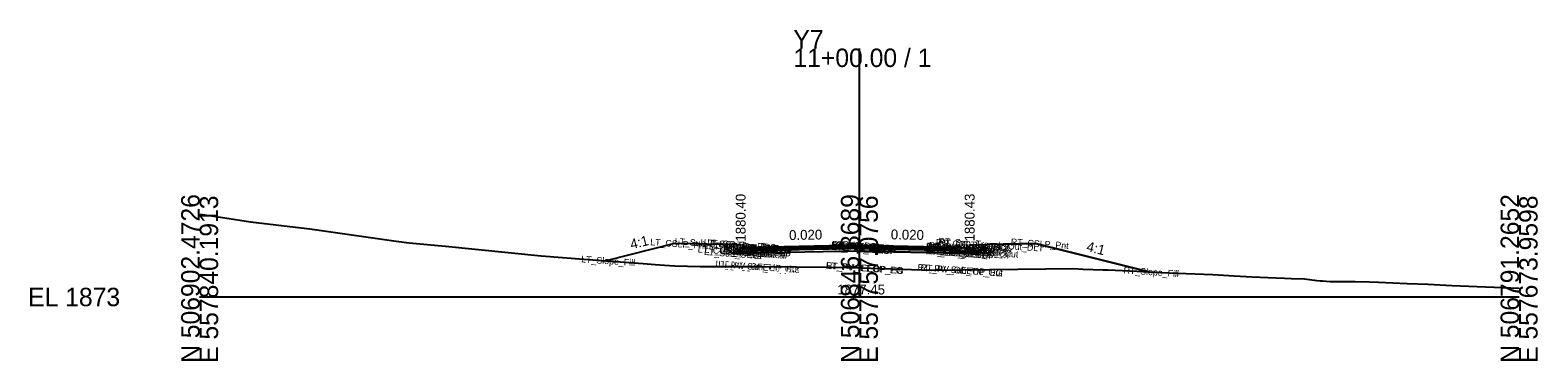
# Model space of a CAD drawing. Extents: x -26 to 557959, y -10 to 506992.
# Drawn here: x -25.7 to 202.8, y 990.3 to 1040.5 of the extents above; entities that cross this region are included whole.
import ezdxf

# ---------------------------------------------------------------- set-up
doc = ezdxf.new("R2010")
doc.units = 0
for name, color, linetype in [('Default', 7, 'Continuous'), ('Exist Cross Section Cell', 7, 'Continuous'), ('Exist XS Center Line Elevation Label', 7, 'Continuous'), ('Exist XS Ground Line', 7, 'Continuous'), ('Prop CMT Conc Surface', 7, 'Continuous'), ('Prop CMT Concrete Structures', 7, 'Continuous'), ('Prop CMT Pvmt Course 1', 7, 'Continuous'), ('Prop CMT Pvmt Course 1 CG', 7, 'Continuous'), ('Prop CMT Pvmt Course 1 Wedge', 7, 'Continuous'), ('Prop CMT Pvmt Course 2', 7, 'Continuous'), ('Prop CMT Pvmt Course 2 Wedge', 7, 'Continuous'), ('Prop CMT Pvmt Course 3', 7, 'Continuous'), ('Prop CMT Pvmt Course 3 Wedge', 7, 'Continuous'), ('Prop CMT Pvmt Surface', 7, 'Continuous'), ('Prop CMT Pvmt Wedge Surface 1', 7, 'Continuous'), ('Prop CMT Pvmt Wedge Surface 2', 7, 'Continuous'), ('Prop CMT Pvmt Wedge Surface 3', 7, 'Continuous'), ('Prop CMT Slope Grass', 7, 'Continuous'), ('Prop CMT Subgrade Earthwork', 7, 'Continuous'), ('Prop XS Earthwork Shape', 7, 'Continuous'), ('Prop XS Hydro Elevations', 7, 'Continuous'), ('Prop XS SE Text', 7, 'Continuous'), ('Prop XS Side Slope Text', 7, 'Continuous'), ('Typical Text Asphalt at Bridge Approach CELL', 7, 'Continuous')]:
    doc.layers.add(name, color=color, linetype=linetype)

msp = doc.modelspace()

# ---------------------------------------------------------------- linework, layer by layer
at = {"layer": 'Exist Cross Section Cell'}
for p, q in [((100, 1000), (100, 1037.69)), ((0, 1000), (100, 1000)), ((100, 1000), (200, 1000))]:
    msp.add_line(p, q, dxfattribs=at)
at = {"layer": 'Exist XS Ground Line'}
for p, q in [((0, 1012.56), (0.41, 1012.51)), ((0.41, 1012.51), (3.8, 1011.99)), ((3.8, 1011.99), (7.72, 1011.38)), ((7.72, 1011.38), (15.4, 1010.47)), ((15.4, 1010.47), (16.71, 1010.33)), ((16.71, 1010.33), (29.77, 1008.49)), ((29.77, 1008.49), (31.75, 1008.22)), ((31.75, 1008.22), (37.25, 1007.73)), ((37.25, 1007.73), (51.75, 1006.26)), ((51.75, 1006.26), (58.24, 1005.74)), ((58.24, 1005.74), (67.24, 1005.08)), ((67.24, 1005.08), (69.06, 1004.94)), ((69.06, 1004.94), (70.46, 1004.81)), ((70.46, 1004.81), (72.01, 1004.73)), ((72.01, 1004.73), (75.86, 1004.63)), ((75.86, 1004.63), (85.17, 1004.62)), ((85.17, 1004.62), (95.78, 1004.52)), ((95.78, 1004.52), (100.23, 1004.44)), ((100.23, 1004.44), (110.96, 1004.08)), ((110.96, 1004.08), (115.55, 1004.1)), ((115.55, 1004.1), (132.5, 1004.3)), ((132.5, 1004.3), (133.88, 1004.24)), ((133.88, 1004.24), (136.97, 1004.1)), ((136.97, 1004.1), (137.34, 1004.11)), ((137.34, 1004.11), (137.65, 1004.1)), ((137.65, 1004.1), (142.05, 1003.94)), ((142.05, 1003.94), (146.83, 1003.65)), ((146.83, 1003.65), (153.56, 1003.43)), ((153.56, 1003.43), (156.8, 1003.21)), ((156.8, 1003.21), (159.52, 1003.07)), ((159.52, 1003.07), (160.76, 1003.03)), ((160.76, 1003.03), (161.9, 1002.96)), ((161.9, 1002.96), (164.45, 1002.85)), ((164.45, 1002.85), (165.45, 1002.81)), ((165.45, 1002.81), (167.49, 1002.74)), ((167.49, 1002.74), (169.35, 1002.48)), ((169.35, 1002.48), (169.82, 1002.44)), ((169.82, 1002.44), (170.2, 1002.44)), ((170.2, 1002.44), (171.35, 1002.35)), ((171.35, 1002.35), (175.17, 1002.33)), ((175.17, 1002.33), (177.3, 1002.32)), ((177.3, 1002.32), (178.7, 1002.26)), ((178.7, 1002.26), (183.05, 1002.06)), ((183.05, 1002.06), (186.23, 1001.92)), ((186.23, 1001.92), (189.81, 1001.76)), ((189.81, 1001.76), (191.1, 1001.71)), ((191.1, 1001.71), (200, 1001.32))]:
    msp.add_line(p, q, dxfattribs=at)
at = {"layer": 'Prop CMT Conc Surface'}
for points in [[(82, 1007.4), (82, 1007.9), (81.5, 1007.9)], [(116.71, 1007.43), (116.72, 1007.93), (117.22, 1007.93)], [(84, 1007.52), (82, 1007.4)], [(114.71, 1007.55), (116.71, 1007.43)]]:
    msp.add_lwpolyline(points, dxfattribs=at)
at = {"layer": 'Prop CMT Concrete Structures'}
for points in [[(84, 1007.52), (82, 1007.4), (82, 1007.9), (81.5, 1007.9)], [(81.5, 1007.9), (81.5, 1006.89), (84, 1006.94)], [(114.71, 1007.55), (116.71, 1007.43), (116.72, 1007.93), (117.22, 1007.93)], [(117.22, 1007.93), (117.21, 1006.91), (114.71, 1006.96)], [(84, 1006.94), (84, 1007.52)], [(114.71, 1006.96), (114.71, 1007.55)]]:
    msp.add_lwpolyline(points, dxfattribs=at)
at = {"layer": 'Prop CMT Pvmt Course 1'}
for points in [[(100, 1007.84), (84, 1007.52)], [(100, 1007.59), (100, 1007.84)], [(100, 1007.84), (114.71, 1007.55)], [(100, 1007.59), (100, 1007.84)], [(84, 1007.4), (100, 1007.72)], [(84, 1007.52), (84, 1007.27), (84, 1007.27), (84, 1007.4)], [(100, 1007.72), (100, 1007.59), (100, 1007.59)], [(114.71, 1007.42), (100, 1007.72)], [(100, 1007.72), (100, 1007.59), (100, 1007.59)], [(114.71, 1007.55), (114.71, 1007.3), (114.71, 1007.3), (114.71, 1007.42)]]:
    msp.add_lwpolyline(points, dxfattribs=at)
at = {"layer": 'Prop CMT Pvmt Course 1 CG'}
for points in [[(84, 1006.94), (81, 1006.88), (80.7, 1006.58)], [(80.7, 1006.58), (84, 1006.65)], [(84, 1006.65), (84, 1006.94)], [(114.71, 1006.96), (117.71, 1006.9), (118.01, 1006.61)], [(114.71, 1006.67), (114.71, 1006.96)], [(118.01, 1006.61), (114.71, 1006.67)]]:
    msp.add_lwpolyline(points, dxfattribs=at)
at = {"layer": 'Prop CMT Pvmt Course 1 Wedge'}
for points in [[(100, 1007.72), (84, 1007.4)], [(100, 1007.72), (114.71, 1007.42)]]:
    msp.add_lwpolyline(points, dxfattribs=at)
at = {"layer": 'Prop CMT Pvmt Course 2'}
for points in [[(84, 1007.02), (84, 1007.02), (84, 1007.27), (84, 1007.27)], [(84, 1007.27), (84, 1007.02)], [(114.71, 1007.05), (114.71, 1007.05), (114.71, 1007.3), (114.71, 1007.3)], [(114.71, 1007.3), (114.71, 1007.05)]]:
    msp.add_lwpolyline(points, dxfattribs=at)
at = {"layer": 'Prop CMT Pvmt Course 2 Wedge'}
for points in [[(100, 1007.59), (84, 1007.27)], [(100, 1007.59), (114.71, 1007.3)]]:
    msp.add_lwpolyline(points, dxfattribs=at)
at = {"layer": 'Prop CMT Pvmt Course 3'}
for points in [[(84, 1007.02), (84, 1007.02), (84, 1006.65), (84, 1006.65)], [(84, 1006.65), (84, 1007.02)], [(114.71, 1007.05), (114.71, 1007.05), (114.71, 1006.67), (114.71, 1006.67)], [(114.71, 1006.67), (114.71, 1007.05)]]:
    msp.add_lwpolyline(points, dxfattribs=at)
at = {"layer": 'Prop CMT Pvmt Course 3 Wedge'}
for points in [[(100, 1007.34), (84, 1007.02)], [(100, 1007.34), (114.71, 1007.05)]]:
    msp.add_lwpolyline(points, dxfattribs=at)
at = {"layer": 'Prop CMT Pvmt Surface'}
for points in [[(100, 1007.84), (84, 1007.52)], [(100, 1007.84), (114.71, 1007.55)]]:
    msp.add_lwpolyline(points, dxfattribs=at)
at = {"layer": 'Prop CMT Pvmt Wedge Surface 1'}
for points in [[(100, 1007.72), (84, 1007.4)], [(84, 1007.27), (84, 1007.52)], [(84, 1007.4), (84, 1007.27), (84, 1007.27)], [(100, 1007.72), (114.71, 1007.42)], [(114.71, 1007.3), (114.71, 1007.55)], [(114.71, 1007.42), (114.71, 1007.3), (114.71, 1007.3)]]:
    msp.add_lwpolyline(points, dxfattribs=at)
at = {"layer": 'Prop CMT Pvmt Wedge Surface 2'}
for points in [[(100, 1007.59), (84, 1007.27)], [(84, 1007.27), (84, 1007.52)], [(100, 1007.59), (114.71, 1007.3)], [(114.71, 1007.3), (114.71, 1007.55)]]:
    msp.add_lwpolyline(points, dxfattribs=at)
at = {"layer": 'Prop CMT Pvmt Wedge Surface 3'}
for points in [[(84, 1007.02), (84, 1007.52)], [(100, 1007.34), (84, 1007.02)], [(100, 1007.34), (114.71, 1007.05)], [(114.71, 1007.05), (114.71, 1007.55)]]:
    msp.add_lwpolyline(points, dxfattribs=at)
at = {"layer": 'Prop CMT Slope Grass'}
for points in [[(81.5, 1007.9), (72, 1008.09), (61.6, 1005.49)], [(117.22, 1007.93), (126.72, 1008.12), (143.86, 1003.83)]]:
    msp.add_lwpolyline(points, dxfattribs=at)
at = {"layer": 'Prop CMT Subgrade Earthwork'}
for points in [[(100, 1006.97), (80.7, 1006.58), (79.34, 1007.95)], [(100, 1006.97), (118.01, 1006.61), (119.38, 1007.97)], [(84, 1006.65), (84, 1006.65)], [(114.71, 1006.67), (114.71, 1006.67)]]:
    msp.add_lwpolyline(points, dxfattribs=at)
at = {"layer": 'Prop XS Earthwork Shape'}
msp.add_lwpolyline([(61.6, 1005.49), (67.24, 1005.08), (69.06, 1004.94), (70.46, 1004.81), (72.01, 1004.73), (75.86, 1004.63), (85.17, 1004.62), (95.78, 1004.52), (100.23, 1004.44), (110.96, 1004.08), (115.55, 1004.1), (132.5, 1004.3), (133.88, 1004.24), (136.97, 1004.1), (137.34, 1004.11), (137.65, 1004.1), (142.05, 1003.94), (143.86, 1003.83), (126.72, 1008.12), (119.38, 1007.97), (118.01, 1006.61), (100, 1006.97), (80.7, 1006.58), (79.34, 1007.95), (72, 1008.09)], close=True, dxfattribs=at)

# ---------------------------------------------------------------- texts
at = {"layer": 'Default'}
msp.add_text('-', height=0.0001, dxfattribs=at).set_placement((0, 1000))
at = {"layer": 'Exist Cross Section Cell'}
for s, p in [('Y7', (90, 1037.69)), ('11+00.00 / 1', (90, 1034.89)), ('EL 1873', (-26, 998.6))]:
    msp.add_text(s, height=2.8, dxfattribs=at).set_placement(p)
for s, p in [('N 506902.4726', (0, 990)), ('E 557840.1913', (2.8, 990)), ('N 506846.8689', (100, 990)), ('E 557757.0756', (102.8, 990)), ('N 506791.2652', (200, 990)), ('E 557673.9598', (202.8, 990))]:
    msp.add_text(s, height=2.8, rotation=90, dxfattribs=at).set_placement(p)
at = {"layer": 'Exist XS Center Line Elevation Label'}
msp.add_text('1877.45', height=1.5, dxfattribs=at).set_placement((96.64, 1000.38))
at = {"layer": 'Prop XS Hydro Elevations'}
for s, p in [('1880.40', (82.75, 1008.4)), ('1880.43', (117.46, 1008.43))]:
    msp.add_text(s, height=1.5, rotation=90, dxfattribs=at).set_placement(p)
at = {"layer": 'Prop XS SE Text'}
for rotation, p in [(1.1458, (89.36, 1008.63)), (358.8542, (104.75, 1008.75))]:
    msp.add_text('0.020', height=1.5, rotation=rotation, dxfattribs=at).set_placement(p)
at = {"layer": 'Prop XS Side Slope Text'}
for rotation, p in [(14.0362, (65.46, 1007.23)), (345.9638, (134.32, 1006.99))]:
    msp.add_text('4:1', height=1.5, rotation=rotation, dxfattribs=at).set_placement(p)
at = {"layer": 'Typical Text Asphalt at Bridge Approach CELL'}
for s, p in [('LT_CSLP_Pnt', (68.27, 1007.85)), ('LT_Sub_Trench_Out_DLT', (71.97, 1007.96)), ('LT_CG_Top_BOC', (76.38, 1007.76)), ('LT_CG_Top_Face', (76.9, 1007.76)), ('LT_CG_Top_Gut', (77.16, 1007.24)), ('LT_PV2_OEEOP', (79.37, 1007.1)), ('LT_PV3_OEEOP', (79.37, 1006.85)), ('LT_PV1_OEEOP', (79.49, 1007.21)), ('LT_PV2_OEOT', (79.72, 1007.07)), ('LT_PV1_OEOT', (79.84, 1007.31)), ('RT_PV2_IEEOP', (95.69, 1007.39)), ('RT_PV3_IEEOP', (95.69, 1007.14)), ('LT_PV2_IEEOP', (95.75, 1007.39)), ('LT_PV3_IEEOP', (95.75, 1007.14)), ('RT_PV1_IEEOP', (95.81, 1007.51)), ('LT_PV1_IEEOP', (95.87, 1007.51)), ('PV2_PGL', (97.32, 1007.28)), ('PV1_PGL', (97.44, 1007.52)), ('RT_PV2_OEEOP', (110.02, 1007.12)), ('RT_PV3_OEEOP', (110.02, 1006.87)), ('RT_PV1_OEEOP', (110.14, 1007.24)), ('RT_PV2_OEOT', (110.38, 1007.1)), ('RT_PV3_OEOT', (110.38, 1006.85)), ('RT_PV1_OEOT', (110.5, 1007.34)), ('RT_CG_Top_Face', (111.55, 1007.79)), ('RT_CG_Top_Gut', (111.82, 1007.27)), ('RT_Sub_Trench_Out_DLT', (111.95, 1007.99)), ('RT_CG_Top_BOC', (112.04, 1007.79)), ('RT_CSLP_Pnt', (122.93, 1007.88)), ('LT_Slope_Fill', (57.81, 1005.26)), ('LT_CG1_Shelf_Out', (75.47, 1006.76)), ('LT_Sub_OEOP', (76.44, 1006.38)), ('LT_CG_Bot_BOC', (76.52, 1006.74)), ('LT_Sub_OEEOP', (79.39, 1006.47)), ('LT_PV3_OEOT', (79.72, 1006.82)), ('LT_Sub_OEOT', (79.75, 1006.44)), ('LT_CG_Bot_IE', (79.9, 1006.72)), ('RT_Sub_OEEOP', (110.05, 1006.5)), ('RT_Sub_OEOT', (110.4, 1006.47)), ('RT_CG_Bot_IE', (110.55, 1006.75)), ('RT_CG1_Shelf_Out', (112.12, 1006.79)), ('RT_CG_Bot_BOC', (112.18, 1006.77)), ('RT_Sub_OEOP', (113.69, 1006.41)), ('LT_PV_Sub_Tie_Out', (78.16, 1004.53)), ('LT_PV_OEEOP_EG', (78.58, 1004.5)), ('RT_PV_IEEOP_EG', (94.9, 1004.3)), ('LT_PV_IEEOP_EG', (94.96, 1004.3)), ('RT_PV_Sub_Tie_Out', (108.79, 1004.01)), ('RT_PV_OEEOP_EG', (109.23, 1003.98)), ('RT_Slope_Fill', (140.02, 1003.6))]:
    msp.add_text(s, height=1, rotation=356, dxfattribs=at).set_placement(p)

doc.saveas('drawing.dxf')
